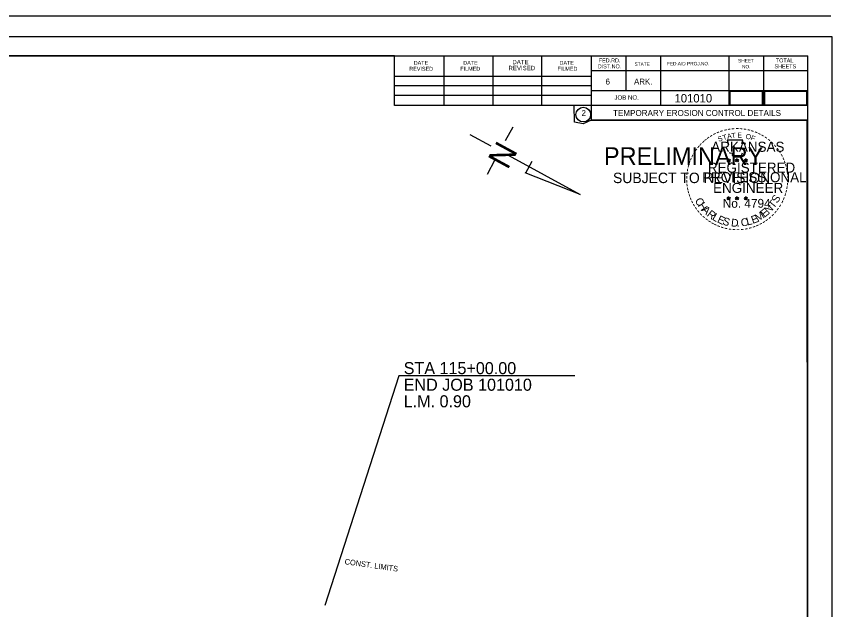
# Model space of a CAD drawing. Extents: x 9844 to 14104, y 9961 to 11067.
# Drawn here: x 10793 to 11605, y 10477 to 11067 of the extents above; entities that cross this region are included whole.
import ezdxf

# ---------------------------------------------------------------- set-up
doc = ezdxf.new("R2010")
doc.units = 0
for name, color, linetype in [('Default', 7, 'Continuous'), ('Page Number', 7, 'Continuous'), ('R_Border', 7, 'Continuous'), ('R_Border Notes', 7, 'Continuous'), ('R_Border Prem', 7, 'Continuous'), ('R_No Plot', 7, 'Continuous'), ('R_NoPlot', 7, 'Continuous'), ('R_Proposed Const Limits Annot', 7, 'Continuous'), ('R_Stamp', 7, 'Continuous'), ('STA Text', 7, 'Continuous'), ('Total_Pages', 7, 'Continuous')]:
    doc.layers.add(name, color=color, linetype=linetype)

msp = doc.modelspace()

# ---------------------------------------------------------------- linework, layer by layer
at = {"layer": 'Default'}
for p, q in [((11244.41, 10949.31), (11265.43, 10937.89)), ((11287.1, 10956.57), (11279.74, 10943.01)), ((11282.76, 10928.48), (11354.25, 10889.65)), ((11269.43, 10924.03), (11261.56, 10909.55)), ((11306.19, 10922.18), (11300.02, 10910.81)), ((11354.25, 10889.65), (11299.64, 10911.03))]:
    msp.add_line(p, q, dxfattribs=at)
at = {"layer": 'Page Number'}
msp.add_lwpolyline([(11503.22, 10978.65), (11535.88, 10978.65), (11535.88, 10991.85), (11503.22, 10991.85)], close=True, dxfattribs=at)
at = {"layer": 'R_Border'}
for p, q in [((11603.9, 11066.7), (9843.9, 11066.7)), ((10000, 11027.3), (11580.9, 11027.3)), ((11169.6, 10977.9), (11169.6, 11027.3)), ((11218.9, 10977.9), (11218.9, 11026.3)), ((11267.7, 10977.9), (11267.7, 11026.3)), ((11316.1, 10977.9), (11316.1, 11026.3)), ((11365.4, 11027.3), (11365.4, 10963.3)), ((11399.6, 11027.3), (11399.6, 10992.6)), ((11434.3, 11027.3), (11434.3, 10977.9)), ((11502.2, 11027.3), (11502.2, 10977.9)), ((11536.9, 11027.3), (11536.9, 10977.9)), ((11580.9, 10000), (11580.9, 11027.3)), ((11169.6, 11007.2), (11365.4, 11007.2)), ((11580.9, 11012.6), (11365.4, 11012.6)), ((11580.9, 11012.7), (11580.9, 11012.7)), ((11169.6, 10997.9), (11365.4, 10997.9)), ((11580.9, 10992.6), (11365.4, 10992.6)), ((11169.6, 10988.2), (11365.4, 10988.2)), ((11580.9, 10977.9), (11169.6, 10977.9)), ((11365.4, 10963.3), (11580.9, 10963.3))]:
    msp.add_line(p, q, dxfattribs=at)
msp.add_circle((11357.33, 10968.98), 7.33, dxfattribs=at)
at = {"layer": 'R_No Plot'}
msp.add_lwpolyline([(10000, 10000), (11580.9, 10000), (11580.3, 10963.3), (11365.4, 10963.3), (11357.31, 10959.87), (11348.49, 10961.4), (11348.26, 10977.9), (11169.6, 10977.9), (11169.6, 11027.3), (10000, 11027.3)], close=True, dxfattribs=at)
msp.add_lwpolyline([(10000, 10000), (11580.9, 10000), (11580.3, 10963.3), (11365.4, 10963.3), (11357.31, 10959.87), (11348.49, 10961.4), (11348.26, 10977.9), (11169.6, 10977.9), (11169.6, 11027.3), (10000, 11027.3)], close=True, dxfattribs=at)
at = {"layer": 'R_NoPlot'}
msp.add_lwpolyline([(9937.96, 11046.77), (11604.66, 11046.77), (11604.66, 9980.09), (9937.96, 9980.09)], close=True, dxfattribs=at)
at = {"layer": 'R_Stamp'}
for p, q in [((11502.05, 10925.31), (11501.85, 10924.05)), ((11502.05, 10923.49), (11502.05, 10925.31)), ((11502.05, 10925.31), (11502.3, 10924.06)), ((11510.4, 10925.31), (11510.2, 10924.05)), ((11510.4, 10923.49), (11510.4, 10925.31)), ((11510.4, 10925.31), (11510.65, 10924.06)), ((11519.22, 10925.25), (11519.02, 10923.99)), ((11519.22, 10923.43), (11519.22, 10925.25)), ((11519.22, 10925.25), (11519.47, 10924)), ((11500.31, 10924.04), (11502.05, 10923.49)), ((11500.31, 10924.04), (11501.57, 10923.82)), ((11500.31, 10924.04), (11501.49, 10923.43)), ((11500.97, 10922), (11502.05, 10923.49)), ((11500.97, 10922), (11501.6, 10923.22)), ((11500.97, 10922), (11502.04, 10923.09)), ((11503.12, 10922), (11502.04, 10923.07)), ((11503.79, 10924.04), (11502.05, 10923.49)), ((11503.12, 10922), (11502.05, 10923.49)), ((11503.79, 10924.04), (11502.36, 10923.8)), ((11503.12, 10922), (11502.43, 10923.46)), ((11503.79, 10924.04), (11502.77, 10923.53)), ((11508.66, 10924.04), (11510.4, 10923.49)), ((11508.66, 10924.04), (11509.92, 10923.82)), ((11508.66, 10924.04), (11509.84, 10923.43)), ((11509.32, 10922), (11510.4, 10923.49)), ((11509.32, 10922), (11509.95, 10923.22)), ((11509.32, 10922), (11510.39, 10923.09)), ((11511.47, 10922), (11510.39, 10923.07)), ((11512.14, 10924.04), (11510.4, 10923.49)), ((11511.47, 10922), (11510.4, 10923.49)), ((11512.14, 10924.04), (11510.71, 10923.8)), ((11511.47, 10922), (11510.78, 10923.46)), ((11512.14, 10924.04), (11511.12, 10923.53)), ((11517.48, 10923.98), (11519.22, 10923.43)), ((11517.48, 10923.98), (11518.74, 10923.76)), ((11517.48, 10923.98), (11518.66, 10923.37)), ((11518.14, 10921.94), (11519.22, 10923.43)), ((11518.14, 10921.94), (11518.77, 10923.16)), ((11518.14, 10921.94), (11519.21, 10923.03)), ((11520.29, 10921.94), (11519.21, 10923.01)), ((11520.96, 10923.98), (11519.22, 10923.43)), ((11520.29, 10921.94), (11519.22, 10923.43)), ((11520.96, 10923.98), (11519.53, 10923.74)), ((11520.29, 10921.94), (11519.6, 10923.4)), ((11520.96, 10923.98), (11519.94, 10923.47)), ((11500.29, 10886.18), (11502.03, 10885.62)), ((11500.29, 10886.18), (11501.55, 10885.95)), ((11500.29, 10886.18), (11501.47, 10885.57)), ((11500.95, 10884.14), (11502.03, 10885.62)), ((11500.95, 10884.14), (11501.58, 10885.36)), ((11500.95, 10884.14), (11502.02, 10885.22)), ((11502.03, 10887.45), (11501.83, 10886.19)), ((11503.1, 10884.14), (11502.02, 10885.21)), ((11502.03, 10885.62), (11502.03, 10887.45)), ((11502.03, 10887.45), (11502.28, 10886.2)), ((11503.77, 10886.18), (11502.03, 10885.62)), ((11503.1, 10884.14), (11502.03, 10885.62)), ((11503.77, 10886.18), (11502.34, 10885.93)), ((11503.1, 10884.14), (11502.41, 10885.59)), ((11503.77, 10886.18), (11502.75, 10885.67)), ((11508.63, 10886.18), (11510.38, 10885.62)), ((11508.63, 10886.18), (11509.9, 10885.95)), ((11508.63, 10886.18), (11509.82, 10885.57)), ((11509.3, 10884.14), (11510.38, 10885.62)), ((11509.3, 10884.14), (11509.93, 10885.36)), ((11509.3, 10884.14), (11510.37, 10885.22)), ((11510.38, 10887.45), (11510.17, 10886.19)), ((11511.44, 10884.14), (11510.37, 10885.21)), ((11510.38, 10885.62), (11510.38, 10887.45)), ((11510.38, 10887.45), (11510.62, 10886.2)), ((11512.11, 10886.18), (11510.38, 10885.62)), ((11511.44, 10884.14), (11510.38, 10885.62)), ((11512.11, 10886.18), (11510.68, 10885.93)), ((11511.44, 10884.14), (11510.76, 10885.59)), ((11512.11, 10886.18), (11511.09, 10885.67)), ((11517.47, 10886.13), (11519.21, 10885.57)), ((11517.47, 10886.13), (11518.73, 10885.9)), ((11517.47, 10886.13), (11518.65, 10885.52)), ((11518.13, 10884.09), (11519.21, 10885.57)), ((11518.13, 10884.09), (11518.76, 10885.31)), ((11518.13, 10884.09), (11519.2, 10885.17)), ((11519.21, 10887.4), (11519.01, 10886.14)), ((11520.28, 10884.09), (11519.2, 10885.16)), ((11519.21, 10885.57), (11519.21, 10887.4)), ((11519.21, 10887.4), (11519.46, 10886.15)), ((11520.95, 10886.13), (11519.21, 10885.57)), ((11520.28, 10884.09), (11519.21, 10885.57)), ((11520.95, 10886.13), (11519.52, 10885.88)), ((11520.28, 10884.09), (11519.59, 10885.54)), ((11520.95, 10886.13), (11519.93, 10885.62))]:
    msp.add_line(p, q, dxfattribs=at)
for points in [[(11500.51, 10943.43), (11501.86, 10939.3)], [(11518.07, 10938.82), (11518.78, 10940.24), (11515.35, 10940.12), (11516.09, 10943.43), (11500.51, 10943.43)], [(11502.05, 10925.31), (11503.12, 10922), (11500.31, 10924.04), (11503.79, 10924.04), (11500.97, 10922), (11502.05, 10925.31)], [(11502.97, 10931.32), (11502.97, 10930.88), (11505.79, 10930.79), (11505.52, 10928.42), (11514.87, 10928.42), (11515.87, 10931.1)], [(11510.4, 10925.31), (11511.47, 10922), (11508.66, 10924.04), (11512.14, 10924.04), (11509.32, 10922), (11510.4, 10925.31)], [(11519.22, 10925.25), (11520.29, 10921.94), (11517.48, 10923.98), (11520.96, 10923.98), (11518.14, 10921.94), (11519.22, 10925.25)], [(11502.03, 10887.45), (11503.1, 10884.14), (11500.29, 10886.18), (11503.77, 10886.18), (11500.95, 10884.14), (11502.03, 10887.45)], [(11510.38, 10887.45), (11511.44, 10884.14), (11508.63, 10886.18), (11512.11, 10886.18), (11509.3, 10884.14), (11510.38, 10887.45)], [(11519.21, 10887.4), (11520.28, 10884.09), (11517.47, 10886.13), (11520.95, 10886.13), (11518.13, 10884.09), (11519.21, 10887.4)]]:
    msp.add_lwpolyline(points, dxfattribs=at)
for centre, radius in [((11502.05, 10923.48), 0.861), ((11502.05, 10923.48), 0.723), ((11502.05, 10923.48), 0.579), ((11502.05, 10923.48), 0.495), ((11502.05, 10923.48), 0.374), ((11502.05, 10923.48), 0.248), ((11502.05, 10923.48), 0.148), ((11510.4, 10923.48), 0.861), ((11510.4, 10923.48), 0.723), ((11510.4, 10923.48), 0.579), ((11510.4, 10923.48), 0.495), ((11510.4, 10923.48), 0.374), ((11510.4, 10923.48), 0.248), ((11510.4, 10923.48), 0.148), ((11519.22, 10923.42), 0.861), ((11519.22, 10923.42), 0.723), ((11519.22, 10923.42), 0.579), ((11519.22, 10923.42), 0.495), ((11519.22, 10923.42), 0.374), ((11519.22, 10923.42), 0.248), ((11519.22, 10923.42), 0.148), ((11502.03, 10885.62), 0.861), ((11502.03, 10885.62), 0.723), ((11502.03, 10885.62), 0.579), ((11502.03, 10885.62), 0.495), ((11502.03, 10885.62), 0.374), ((11502.03, 10885.62), 0.248), ((11502.03, 10885.62), 0.148), ((11510.37, 10885.62), 0.861), ((11510.37, 10885.62), 0.723), ((11510.37, 10885.62), 0.579), ((11510.37, 10885.62), 0.495), ((11510.37, 10885.62), 0.374), ((11510.37, 10885.62), 0.248), ((11510.37, 10885.62), 0.148), ((11519.21, 10885.57), 0.861), ((11519.21, 10885.57), 0.723), ((11519.21, 10885.57), 0.579), ((11519.21, 10885.57), 0.495), ((11519.21, 10885.57), 0.374), ((11519.21, 10885.57), 0.248), ((11519.21, 10885.57), 0.148)]:
    msp.add_circle(centre, radius, dxfattribs=at)
at = {"layer": 'STA Text'}
msp.add_lwpolyline([(11348.91, 10709.13), (11173.68, 10709.13), (11100, 10480.99)], dxfattribs=at)
at = {"layer": 'Total_Pages'}
msp.add_lwpolyline([(11537.72, 10978.65), (11580.08, 10978.65), (11580.08, 10991.85), (11537.72, 10991.85)], close=True, dxfattribs=at)

# ---------------------------------------------------------------- texts
at = {"layer": 'Default'}
msp.add_text('N', height=23.27, rotation=241.48958, dxfattribs=at).set_placement((11272.24, 10944.23))
at = {"layer": 'R_Border'}
for s, height, p in [('DATE', 3.91, (11188.6, 11018.5)), ('DATE', 3.91, (11237.9, 11018.5)), ('DATE', 4.396, (11286.8, 11019)), ('DATE', 3.91, (11333.7, 11018.5)), ('FED.RD.', 3.91, (11372.8, 11020.9)), ('SHEET', 3.42, (11511.5, 11020.9)), ('TOTAL', 3.91, (11549.1, 11020.9)), ('REVISED', 3.91, (11184.2, 11012.59)), ('FILMED', 3.91, (11235, 11012.59)), ('REVISED', 4.396, (11282.9, 11013.09)), ('FILMED', 3.91, (11331.7, 11012.59)), ('DIST.NO.', 3.91, (11371.8, 11015)), ('STATE', 3.42, (11408.4, 11017.5)), ('FED.AID PROJ.NO.', 3.42, (11440.7, 11018)), ('NO.', 3.42, (11515.4, 11015)), ('SHEETS', 3.91, (11547.7, 11015)), ('6', 5.86, (11379.6, 10998.9)), ('ARK.', 5.861, (11407.9, 10998.9)), ('JOB NO.', 4.396, (11388.4, 10983.8)), ('2', 5.86, (11355.7, 10967.69))]:
    msp.add_text(s, height=height, dxfattribs=at).set_placement(p)
at = {"layer": 'R_Border Notes'}
for s, height, p in [('101010', 8.4, (11448.18, 10981.05)), ('TEMPORARY EROSION CONTROL DETAILS', 6, (11387.05, 10967.6))]:
    msp.add_text(s, height=height, dxfattribs=at).set_placement(p)
at = {"layer": 'R_Border Prem'}
for s, height, p in [('PRELIMINARY', 17.5, (11377.93, 10919.01)), ('SUBJECT TO REVISION', 10.3756, (11386.98, 10900.86))]:
    msp.add_text(s, height=height, dxfattribs=at).set_placement(p)
at = {"layer": 'R_Proposed Const Limits Annot'}
msp.add_text('CONST. LIMITS', height=5.5, rotation=351.9155, dxfattribs=at).set_placement((11119.59, 10521.97))
at = {"layer": 'R_Stamp'}
for s, height, rotation, p in [('-', 8, 28.79182, (11487.92, 10946.14)), ('-', 8, 24.30721, (11491.08, 10947.72)), ('-', 8, 19.17608, (11494.25, 10949.07)), ('T', 5, 16.4036, (11496.86, 10943.48)), ('-', 8, 13.63015, (11498, 10950.27)), ('A', 5, 11.21318, (11500.99, 10944.73)), ('-', 8, 10.21935, (11501.39, 10951.08)), ('T', 5, 6.02276, (11505.23, 10945.56)), ('-', 8, 5.89682, (11505.04, 10951.63)), ('-', 8, 0.18623, (11508.9, 10951.99)), ('E', 5, 0.83234, (11510.76, 10946.11)), ('-', 8, 357.74304, (11512.51, 10951.93)), ('-', 8, 352.16172, (11516.23, 10951.65)), ('O', 5, 350.4515, (11518.78, 10945.06)), ('-', 8, 347.20489, (11519.83, 10951.08)), ('-', 8, 342.3362, (11523, 10950.3)), ('-', 8, 337.85509, (11526.68, 10949.19)), ('-', 8, 334.12109, (11529.83, 10947.83)), ('-', 8, 42.96224, (11477.5, 10938.34)), ('-', 8, 38.95066, (11479.66, 10940.42)), ('-', 8, 36.23174, (11482.04, 10942.31)), ('-', 8, 34.06357, (11484.93, 10944.29)), ('S', 5, 21.59401, (11492.29, 10941.82)), ('F', 5, 340.07066, (11523.55, 10943.92)), ('-', 8, 329.64089, (11532.73, 10946.42)), ('-', 8, 325.86266, (11535.94, 10944.61)), ('-', 8, 320.52971, (11538.99, 10942.48)), ('-', 8, 315.57859, (11541.99, 10940.04)), ('-', 8, 54.23247, (11471.18, 10930.68)), ('-', 8, 50.61417, (11473.24, 10933.52)), ('-', 8, 48.42305, (11475.26, 10935.95)), ('-', 8, 309.87973, (11544.83, 10937.29)), ('-', 8, 306.65218, (11547.46, 10934.28)), ('-', 8, 67.77427, (11466.69, 10921.92)), ('-', 8, 62.87135, (11467.99, 10924.98)), ('-', 8, 58.07063, (11469.55, 10928.05)), ('-', 7, 303.67529, (11549.89, 10931.44)), ('-', 8, 299.66835, (11551.48, 10928.41)), ('-', 8, 294.66279, (11553.1, 10925.35)), ('-', 8, 75.46096, (11464.61, 10915.2)), ('-', 8, 72.39447, (11465.6, 10918.77)), ('-', 8, 290.57283, (11554.39, 10922.46)), ('-', 8, 285.12326, (11555.56, 10919.56)), ('-', 8, 85.18634, (11463.57, 10908.18)), ('-', 8, 81.20126, (11463.95, 10911.64)), ('-', 8, 280.54934, (11556.56, 10915.85)), ('-', 8, 276.59616, (11557.37, 10912.01)), ('-', 8, 94.19588, (11463.62, 10901.05)), ('-', 8, 89.06224, (11463.45, 10904.68)), ('-', 8, 263.5172, (11557.74, 10901.91)), ('-', 8, 274.33011, (11557.67, 10908.4)), ('-', 8, 269.94067, (11557.84, 10905.24)), ('-', 8, 98.94793, (11463.98, 10897.72)), ('-', 8, 101.71495, (11464.66, 10894.05)), ('-', 8, 105.45785, (11465.47, 10891.08)), ('-', 8, 255.7626, (11556.84, 10895.25)), ('-', 8, 260.99529, (11557.39, 10898.64)), ('-', 8, 109.08742, (11466.54, 10887.92)), ('-', 8, 114.06432, (11467.81, 10884.94)), ('C', 7.7, 296.9133, (11468.18, 10883.9)), ('T', 7.7, 51.51144, (11546.85, 10875.07)), ('S', 7.7, 57.878, (11550.49, 10880.28)), ('-', 8, 247.88866, (11554.82, 10888.29)), ('-', 8, 255.7626, (11555.88, 10891.81)), ('-', 8, 115.72885, (11469.34, 10881.85)), ('-', 8, 120.44712, (11471.12, 10878.92)), ('-', 8, 125.89344, (11473.14, 10876.12)), ('H', 7.7, 303.27986, (11471.13, 10878.7)), ('A', 7.7, 316.01299, (11474.77, 10873.57)), ('N', 7.7, 45.14487, (11542.05, 10869.86)), ('-', 8, 239.07125, (11551.54, 10881.38)), ('-', 8, 244.61971, (11553.51, 10885.14)), ('-', 8, 130.71812, (11475.45, 10873.36)), ('-', 8, 134.22381, (11478.03, 10870.63)), ('-', 8, 138.93382, (11480.66, 10868.31)), ('R', 7.7, 322.37955, (11479.9, 10868.66)), ('L', 7.7, 328.74612, (11485.03, 10864.91)), ('E', 7.7, 335.11268, (11490.06, 10862.12)), ('E', 7.7, 19.67862, (11526.09, 10860.26)), ('M', 7.7, 32.41175, (11531.2, 10862.15)), ('E', 7.7, 38.77831, (11537.6, 10866.21)), ('-', 8, 225.76533, (11544.98, 10872.47)), ('-', 8, 231.25377, (11547.38, 10875.29)), ('-', 8, 233.84524, (11549.53, 10878.12)), ('-', 8, 144.64634, (11483.44, 10866.28)), ('-', 8, 148.08978, (11486.24, 10864.43)), ('-', 8, 151.57039, (11489.14, 10862.8)), ('-', 8, 154.60019, (11491.75, 10861.57)), ('S', 7.7, 341.47924, (11495.39, 10859.96)), ('D', 7.7, 354.21237, (11504.22, 10857.9)), ('C', 7.7, 6.94549, (11514.65, 10857.71)), ('L', 7.7, 13.31206, (11520.57, 10858.66)), ('-', 8, 207.35684, (11534.17, 10863.9)), ('-', 8, 212.24909, (11536.96, 10865.63)), ('-', 8, 215.73633, (11539.63, 10867.56)), ('-', 8, 221.08509, (11542.37, 10869.92)), ('-', 8, 158.56121, (11494.87, 10860.3)), ('-', 8, 162.79826, (11498.3, 10859.23)), ('-', 8, 167.55551, (11501.88, 10858.41)), ('-', 8, 173.11546, (11505.74, 10857.86)), ('-', 8, 176.51827, (11509.48, 10857.6)), ('-', 8, 181.59176, (11513.2, 10857.69)), ('.', 7.7, 0.57893, (11510.09, 10857.52)), ('-', 8, 185.81666, (11517.24, 10858.07)), ('-', 8, 191.28576, (11520.92, 10858.73)), ('-', 8, 195.47429, (11524.57, 10859.73)), ('-', 8, 200.71842, (11527.95, 10860.94)), ('-', 8, 204.25161, (11531.05, 10862.3))]:
    msp.add_text(s, height=height, rotation=rotation, dxfattribs=at).set_placement(p)
for s, height, p in [('ARKANSAS', 10, (11484.78, 10931.99)), ('REGISTERED', 10, (11481.39, 10911.25)), ('PROFESSIONAL', 10, (11475.65, 10901.73)), ('ENGINEER', 10, (11486.58, 10891.1)), ('No. 4794', 8.785, (11496.21, 10876.35))]:
    msp.add_text(s, height=height, dxfattribs=at).set_placement(p)
at = {"layer": 'STA Text'}
for s, p in [('STA 115+00.00', (11178.64, 10710.88)), ('END JOB 101010', (11178.64, 10694.38)), ('L.M. 0.90', (11178.64, 10677.88))]:
    msp.add_text(s, height=12, dxfattribs=at).set_placement(p)

doc.saveas('drawing.dxf')
